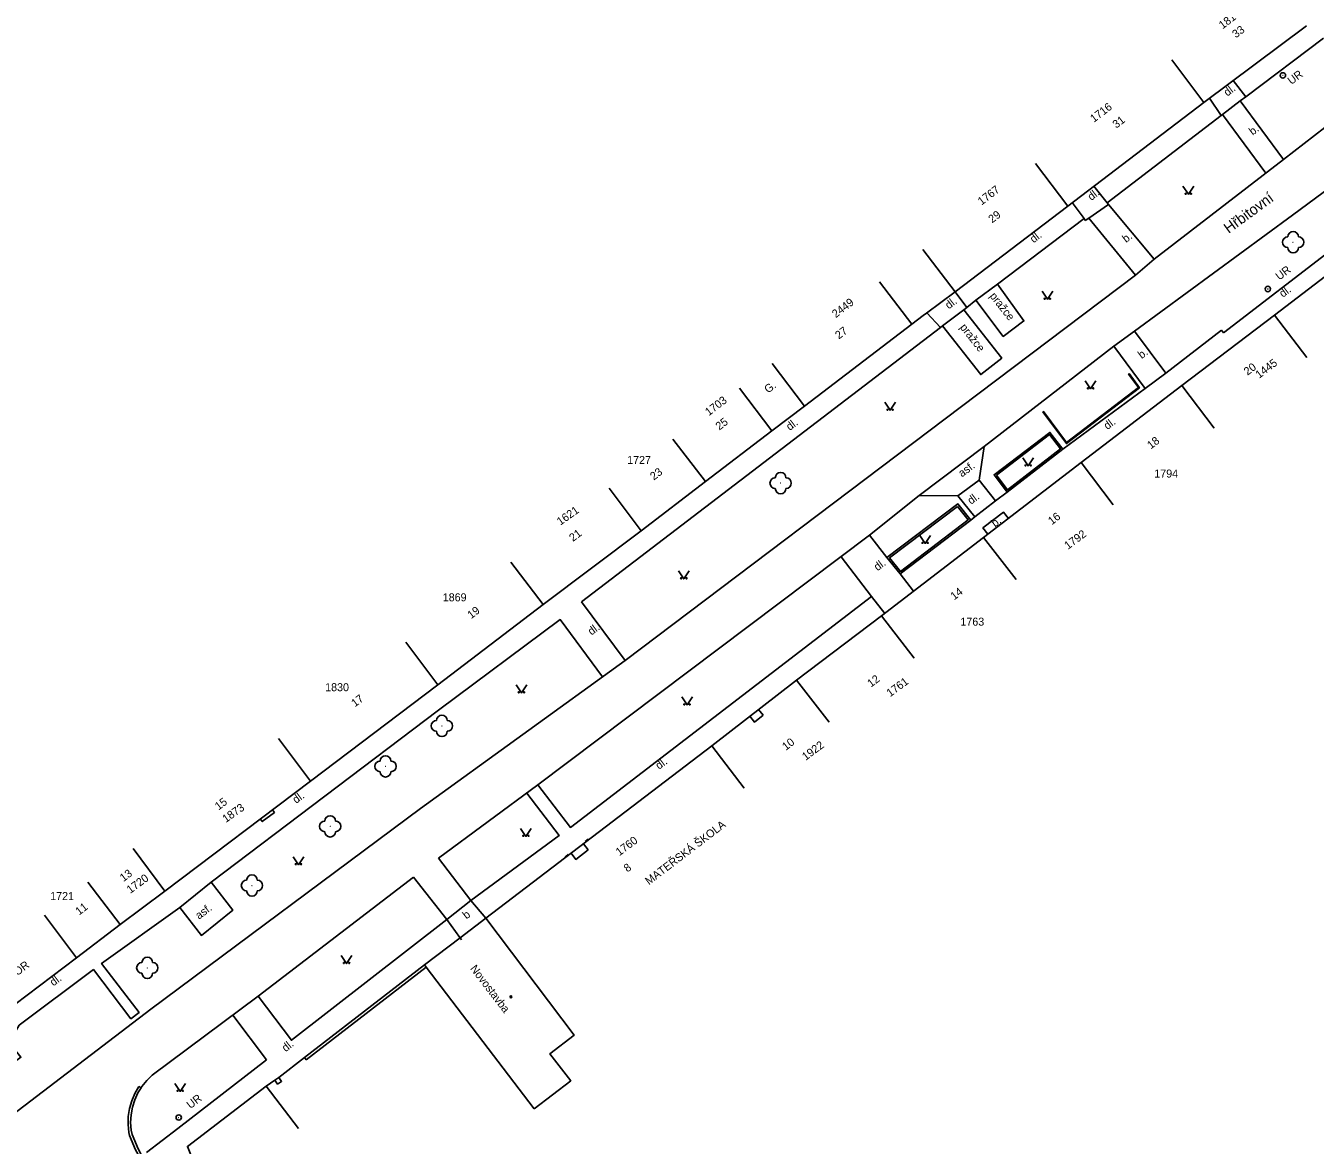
# Model space of a CAD drawing. Extents: x -584400 to -581602, y -1210894 to -1208793.
# Drawn here: x -582510.6 to -582389.8, y -1209260.4 to -1209155.5 of the extents above; entities that cross this region are included whole.
import ezdxf

# ---------------------------------------------------------------- set-up
doc = ezdxf.new("R2010")
doc.units = 0
for name, color, linetype in [('BUDOVY_MĚŘ', 7, 'Continuous'), ('NÁZVY_ULIC_TOK_SMĚR', 7, 'Continuous'), ('POMOC_POPIS', 7, 'Continuous'), ('ROZHRANÍ_PLOCH', 7, 'Continuous'), ('ZELEŇ', 7, 'Continuous'), ('ZN_BUDOV', 7, 'Continuous'), ('ZN_DOPLŇKOVÉ', 7, 'Continuous'), ('ZN_KULTUR', 7, 'Continuous'), ('Č_POPIS_EVID', 7, 'Continuous')]:
    doc.layers.add(name, color=color, linetype=linetype)

msp = doc.modelspace()

# ---------------------------------------------------------------- linework, layer by layer
at = {"layer": 'BUDOVY_MĚŘ'}
for points in [[(-582400.2, -1209162.7), (-582390.58, -1209155.51)], [(-582403.19, -1209158.7), (-582400.2, -1209162.7)], [(-582412.94, -1209172.41), (-582400.2, -1209162.7)], [(-582415.97, -1209168.43), (-582412.94, -1209172.41)], [(-582393.57, -1209182.62), (-582377.75, -1209170.54)], [(-582426.53, -1209176.46), (-582423.5, -1209180.44), (-582412.94, -1209172.41)], [(-582430.59, -1209179.49), (-582427.56, -1209183.47)], [(-582437.6, -1209191.13), (-582427.56, -1209183.47)], [(-582402.25, -1209189.22), (-582393.57, -1209182.62)], [(-582390.54, -1209186.59), (-582393.57, -1209182.62)], [(-582440.63, -1209187.15), (-582437.6, -1209191.13)], [(-582440.67, -1209193.46), (-582443.71, -1209189.47)], [(-582411.69, -1209196.42), (-582402.25, -1209189.22)], [(-582399.22, -1209193.2), (-582402.25, -1209189.22)], [(-582440.67, -1209193.46), (-582437.6, -1209191.13)], [(-582446.9, -1209198.2), (-582449.94, -1209194.23)], [(-582446.9, -1209198.2), (-582440.67, -1209193.46)], [(-582420.82, -1209203.43), (-582411.69, -1209196.42)], [(-582408.67, -1209200.39), (-582411.69, -1209196.42)], [(-582452.92, -1209202.81), (-582446.9, -1209198.2)], [(-582452.92, -1209202.81), (-582455.93, -1209198.82)], [(-582462.1, -1209209.73), (-582452.92, -1209202.81)], [(-582430.39, -1209210.79), (-582420.82, -1209203.43)], [(-582417.78, -1209207.39), (-582420.82, -1209203.43)], [(-582462.1, -1209209.73), (-582465.13, -1209205.75)], [(-582471.97, -1209217.25), (-582462.1, -1209209.73)], [(-582430.39, -1209210.79), (-582438.36, -1209216.8)], [(-582427.34, -1209214.75), (-582430.39, -1209210.79)], [(-582471.97, -1209217.25), (-582474.98, -1209213.26)], [(-582483.9, -1209226.26), (-582471.97, -1209217.25)], [(-582438.36, -1209216.8), (-582446.28, -1209222.95)], [(-582438.36, -1209216.8), (-582435.3, -1209220.75)], [(-582483.9, -1209226.26), (-582486.91, -1209222.27)], [(-582446.28, -1209222.95), (-582467.47, -1209239.11)], [(-582446.28, -1209222.95), (-582443.25, -1209226.92)], [(-582497.54, -1209236.56), (-582483.9, -1209226.26)], [(-582497.54, -1209236.56), (-582500.53, -1209232.56)], [(-582501.73, -1209239.69), (-582504.76, -1209235.71)], [(-582501.73, -1209239.69), (-582497.54, -1209236.56)], [(-582505.82, -1209242.8), (-582508.83, -1209238.81)], [(-582467.47, -1209239.11), (-582469.88, -1209240.94), (-582473.22, -1209243.48), (-582473.07, -1209243.68), (-582462.93, -1209256.94)], [(-582467.47, -1209239.11), (-582459.2, -1209250.06), (-582461.46, -1209251.79), (-582459.51, -1209254.33), (-582462.93, -1209256.94)], [(-582505.82, -1209242.8), (-582501.73, -1209239.69)], [(-582515.1, -1209249.79), (-582505.82, -1209242.8)], [(-582488.06, -1209254.83), (-582495.44, -1209260.47), (-582489.61, -1209275.17)], [(-582488.06, -1209254.83), (-582485.03, -1209258.81)]]:
    msp.add_lwpolyline(points, dxfattribs=at)
at = {"layer": 'ROZHRANÍ_PLOCH'}
for points in [[(-582392.73, -1209168.05), (-582380.13, -1209158.29), (-582375.26, -1209154.89), (-582365.39, -1209148.17), (-582355.61, -1209141), (-582340.78, -1209130.73)], [(-582396.24, -1209162.16), (-582388.96, -1209156.68)], [(-582406.67, -1209184.13), (-582391.87, -1209173.27), (-582380.85, -1209165.11), (-582372.27, -1209159.23)], [(-582397.45, -1209160.65), (-582396.24, -1209162.16)], [(-582399.66, -1209162.3), (-582398.56, -1209163.93)], [(-582398.44, -1209163.84), (-582396.77, -1209162.56)], [(-582396.77, -1209162.56), (-582396.24, -1209162.16)], [(-582396.77, -1209162.56), (-582392.73, -1209168.05)], [(-582409.24, -1209172.1), (-582398.56, -1209163.93)], [(-582398.56, -1209163.93), (-582398.44, -1209163.84)], [(-582398.44, -1209163.84), (-582394.39, -1209169.33)], [(-582404.83, -1209177.37), (-582392.73, -1209168.05)], [(-582410.5, -1209170.54), (-582409.24, -1209172.1)], [(-582411.4, -1209173.57), (-582412.52, -1209172.08)], [(-582410.98, -1209173.54), (-582409.11, -1209172.25)], [(-582409.11, -1209172.25), (-582409.24, -1209172.1)], [(-582404.83, -1209177.37), (-582409.11, -1209172.25)], [(-582419.52, -1209179.71), (-582411.4, -1209173.57)], [(-582411.4, -1209173.57), (-582411.3, -1209173.74)], [(-582410.98, -1209173.54), (-582411.3, -1209173.74)], [(-582410.98, -1209173.54), (-582406.6, -1209178.86)], [(-582398.34, -1209184.27), (-582387.93, -1209176.29)], [(-582406.6, -1209178.86), (-582404.83, -1209177.37)], [(-582422.91, -1209191.16), (-582406.6, -1209178.86)], [(-582419.52, -1209179.71), (-582417.05, -1209183.16), (-582418.98, -1209184.61), (-582421.56, -1209181.23)], [(-582421.56, -1209181.23), (-582419.52, -1209179.71)], [(-582423.5, -1209180.44), (-582422.4, -1209181.9)], [(-582422.4, -1209181.9), (-582421.56, -1209181.23)], [(-582426.15, -1209182.4), (-582424.88, -1209183.77)], [(-582424.69, -1209183.63), (-582422.68, -1209182.12)], [(-582422.68, -1209182.12), (-582419.13, -1209186.64), (-582421.1, -1209188.19), (-582424.69, -1209183.63)], [(-582422.68, -1209182.12), (-582422.4, -1209181.9)], [(-582424.69, -1209183.63), (-582424.88, -1209183.77)], [(-582424.88, -1209183.77), (-582458.5, -1209209.48)], [(-582408.61, -1209185.52), (-582406.67, -1209184.13)], [(-582406.67, -1209184.13), (-582403.75, -1209188.06)], [(-582403.75, -1209188.06), (-582398.53, -1209184.03)], [(-582398.34, -1209184.27), (-582398.53, -1209184.03)], [(-582420.77, -1209194.93), (-582408.61, -1209185.52)], [(-582408.61, -1209185.52), (-582405.69, -1209189.49)], [(-582415.26, -1209191.69), (-582413.07, -1209194.65), (-582406.23, -1209189.42), (-582407.18, -1209188.1)], [(-582415.26, -1209191.69), (-582415.2, -1209191.65), (-582413.05, -1209194.55), (-582406.32, -1209189.4), (-582407.24, -1209188.14), (-582407.18, -1209188.1)], [(-582405.69, -1209189.49), (-582403.75, -1209188.06)], [(-582405.69, -1209189.49), (-582413.41, -1209195.18)], [(-582422.91, -1209191.16), (-582454.42, -1209214.96)], [(-582413.41, -1209195.18), (-582414.61, -1209193.6), (-582419.84, -1209197.57), (-582418.62, -1209199.2)], [(-582419.63, -1209197.6), (-582418.59, -1209198.99), (-582413.62, -1209195.15), (-582414.64, -1209193.81), (-582419.63, -1209197.6)], [(-582426.85, -1209199.52), (-582420.77, -1209194.93)], [(-582421.24, -1209198.06), (-582420.77, -1209194.93)], [(-582418.62, -1209199.2), (-582413.41, -1209195.18)], [(-582423.24, -1209199.55), (-582421.24, -1209198.06)], [(-582419.7, -1209200), (-582421.24, -1209198.06)], [(-582418.62, -1209199.2), (-582419.7, -1209200)], [(-582431.52, -1209203.24), (-582426.85, -1209199.52)], [(-582422.03, -1209201.81), (-582423.24, -1209200.3), (-582429.88, -1209205.33)], [(-582423.27, -1209200.53), (-582429.63, -1209205.36), (-582428.62, -1209206.62), (-582422.27, -1209201.78), (-582423.27, -1209200.53)], [(-582426.85, -1209199.52), (-582423.24, -1209199.55)], [(-582423.24, -1209199.55), (-582421.66, -1209201.52)], [(-582421.66, -1209201.52), (-582419.7, -1209200)], [(-582428.64, -1209206.85), (-582422.03, -1209201.81)], [(-582421.66, -1209201.52), (-582422.03, -1209201.81)], [(-582418.5, -1209201.65), (-582418.95, -1209201.08), (-582420.89, -1209202.55), (-582420.44, -1209203.14)], [(-582462.59, -1209226.62), (-582431.52, -1209203.24)], [(-582429.88, -1209205.33), (-582431.52, -1209203.24)], [(-582434.17, -1209205.24), (-582431.32, -1209208.96)], [(-582429.88, -1209205.33), (-582428.64, -1209206.85)], [(-582427.39, -1209208.48), (-582428.64, -1209206.85)], [(-582431.32, -1209208.96), (-582459.55, -1209230.59), (-582462.59, -1209226.62)], [(-582430.09, -1209210.56), (-582431.32, -1209208.96)], [(-582454.42, -1209214.96), (-582458.5, -1209209.48)], [(-582493.2, -1209235.73), (-582471.92, -1209219.63), (-582460.5, -1209211.14), (-582456.53, -1209216.49)], [(-582454.42, -1209214.96), (-582473.58, -1209228.82), (-582498.86, -1209247.61), (-582520.87, -1209264.4), (-582538.55, -1209278.13)], [(-582441.49, -1209220.09), (-582441.91, -1209219.55)], [(-582441.49, -1209220.09), (-582442.31, -1209220.73), (-582442.73, -1209220.19)], [(-582471.92, -1209233.48), (-582462.59, -1209226.62)], [(-582463.64, -1209227.38), (-582460.6, -1209231.35), (-582468.88, -1209237.44), (-582467.47, -1209239.11)], [(-582487.47, -1209228.95), (-582487.28, -1209229.19), (-582488.42, -1209230.05), (-582488.6, -1209229.81)], [(-582458.16, -1209231.92), (-582457.89, -1209231.71), (-582457.84, -1209231.77)], [(-582458.16, -1209231.92), (-582458.11, -1209231.97)], [(-582459.75, -1209233.13), (-582460.02, -1209233.34), (-582459.97, -1209233.39)], [(-582459.75, -1209233.13), (-582459.7, -1209233.19)], [(-582457.89, -1209232.71), (-582459.04, -1209233.59), (-582459.48, -1209233.02)], [(-582457.89, -1209232.71), (-582458.33, -1209232.14)], [(-582471.92, -1209233.48), (-582468.88, -1209237.44)], [(-582488.82, -1209246.4), (-582474.25, -1209235.27)], [(-582471.14, -1209239.23), (-582474.25, -1209235.27)], [(-582493.2, -1209235.73), (-582491.17, -1209238.34), (-582494.13, -1209240.72), (-582496.16, -1209238.11)], [(-582496.16, -1209238.11), (-582493.2, -1209235.73)], [(-582541.38, -1209275.07), (-582520.64, -1209259.31), (-582511.04, -1209252.13), (-582512.14, -1209250.73), (-582511.19, -1209249.12), (-582504.25, -1209243.91), (-582500.73, -1209248.51), (-582499.97, -1209247.92), (-582503.48, -1209243.34), (-582496.16, -1209238.11)], [(-582468.88, -1209237.44), (-582471.14, -1209239.23)], [(-582471.14, -1209239.23), (-582485.7, -1209250.53), (-582488.82, -1209246.4)], [(-582471.14, -1209239.23), (-582469.9, -1209240.92)], [(-582498.73, -1209253.81), (-582488.82, -1209246.4)], [(-582491.19, -1209248.17), (-582488.02, -1209252.37)], [(-582499.27, -1209261.03), (-582496.35, -1209258.8), (-582488.02, -1209252.37)], [(-582498.73, -1209253.81), (-582499.25, -1209254.3), (-582499.7, -1209254.86), (-582499.78, -1209254.99)], [(-582499.98, -1209254.86), (-582500.36, -1209255.51), (-582500.66, -1209256.2), (-582500.86, -1209256.92), (-582500.98, -1209257.67), (-582501, -1209258.42), (-582500.92, -1209259.17), (-582500.87, -1209259.44), (-582500.29, -1209260.81), (-582499.54, -1209262.1), (-582498.84, -1209263.05)], [(-582499.78, -1209254.99), (-582500.08, -1209255.47), (-582500.38, -1209256.12), (-582500.59, -1209256.8), (-582500.72, -1209257.51), (-582500.76, -1209258.23), (-582500.7, -1209258.94), (-582500.63, -1209259.36), (-582500.06, -1209260.7), (-582499.71, -1209261.36)], [(-582499.98, -1209254.86), (-582499.78, -1209254.99)]]:
    msp.add_lwpolyline(points, dxfattribs=at)
at = {"layer": 'ZELEŇ'}
for centre in [(-582391.82, -1209175.79), (-582439.85, -1209198.35), (-582471.59, -1209221.09), (-582476.87, -1209224.88), (-582482.06, -1209230.5), (-582489.39, -1209236.04), (-582499.2, -1209243.75)]:
    msp.add_circle(centre, 0.0005, dxfattribs=at)
for centre, start, end in [((-582392.32, -1209175.79), 90, 270), ((-582391.82, -1209175.29), 0, 180), ((-582391.32, -1209175.79), 270, 90), ((-582391.82, -1209176.29), 180, 360), ((-582440.35, -1209198.35), 90, 270), ((-582439.85, -1209197.85), 0, 180), ((-582439.35, -1209198.35), 270, 90), ((-582439.85, -1209198.85), 180, 360), ((-582472.09, -1209221.09), 90, 270), ((-582471.59, -1209220.59), 0, 180), ((-582471.09, -1209221.09), 270, 90), ((-582471.59, -1209221.59), 180, 360), ((-582477.37, -1209224.88), 90, 270), ((-582476.87, -1209224.38), 0, 180), ((-582476.37, -1209224.88), 270, 90), ((-582476.87, -1209225.38), 180, 360), ((-582482.06, -1209230), 0, 180), ((-582482.56, -1209230.5), 90, 270), ((-582481.56, -1209230.5), 270, 90), ((-582482.06, -1209231), 180, 360), ((-582489.89, -1209236.04), 90, 270), ((-582489.39, -1209235.54), 0, 180), ((-582488.89, -1209236.04), 270, 90), ((-582489.39, -1209236.54), 180, 360), ((-582499.2, -1209243.25), 0, 180), ((-582499.7, -1209243.75), 90, 270), ((-582498.7, -1209243.75), 270, 90), ((-582499.2, -1209244.25), 180, 360)]:
    msp.add_arc(centre, 0.5, start, end, dxfattribs=at)
at = {"layer": 'ZN_BUDOV'}
msp.add_circle((-582465.12, -1209246.46), 0.0875, dxfattribs=at)
at = {"layer": 'ZN_DOPLŇKOVÉ'}
for points in [[(-582426.19, -1209182.43), (-582423.5, -1209180.44)], [(-582426.5, -1209182.66), (-582426.19, -1209182.43)], [(-582427.56, -1209183.47), (-582426.5, -1209182.66)], [(-582469.88, -1209240.94), (-582469.75, -1209241.12)], [(-582484.31, -1209252.35), (-582484.47, -1209252.15), (-582473.22, -1209243.48)], [(-582473.07, -1209243.68), (-582484.31, -1209252.35)], [(-582484.47, -1209252.15), (-582486.88, -1209254.01)], [(-582487.25, -1209254.27), (-582488.06, -1209254.83)], [(-582487.25, -1209254.27), (-582486.88, -1209254.01), (-582486.62, -1209254.38), (-582486.99, -1209254.64), (-582487.25, -1209254.27)]]:
    msp.add_lwpolyline(points, dxfattribs=at)
for centre, radius in [((-582392.78, -1209160.16), 0.25), ((-582392.78, -1209160.16), 0.0005), ((-582394.19, -1209180.17), 0.25), ((-582394.19, -1209180.17), 0.0005), ((-582496.25, -1209257.77), 0.25), ((-582496.25, -1209257.77), 0.0005)]:
    msp.add_circle(centre, radius, dxfattribs=at)
at = {"layer": 'ZN_KULTUR'}
for points in [[(-582402.14, -1209170.55), (-582401.64, -1209171.3), (-582401.14, -1209170.55)], [(-582415.35, -1209180.38), (-582414.85, -1209181.13), (-582414.35, -1209180.38)], [(-582411.3, -1209188.77), (-582410.8, -1209189.52), (-582410.3, -1209188.77)], [(-582430.09, -1209190.78), (-582429.59, -1209191.53), (-582429.09, -1209190.78)], [(-582417.15, -1209195.99), (-582416.65, -1209196.74), (-582416.15, -1209195.99)], [(-582426.8, -1209203.25), (-582426.3, -1209204), (-582425.8, -1209203.25)], [(-582449.42, -1209206.57), (-582448.92, -1209207.32), (-582448.42, -1209206.57)], [(-582464.64, -1209217.25), (-582464.14, -1209218), (-582463.64, -1209217.25)], [(-582449.12, -1209218.38), (-582448.62, -1209219.13), (-582448.12, -1209218.38)], [(-582464.22, -1209230.69), (-582463.72, -1209231.44), (-582463.22, -1209230.69)], [(-582485.53, -1209233.34), (-582485.03, -1209234.09), (-582484.53, -1209233.34)], [(-582481.02, -1209242.6), (-582480.52, -1209243.35), (-582480.02, -1209242.6)], [(-582496.61, -1209254.57), (-582496.11, -1209255.32), (-582495.61, -1209254.57)]]:
    msp.add_lwpolyline(points, dxfattribs=at)
for centre in [(-582401.89, -1209171.25), (-582401.39, -1209171.25), (-582415.1, -1209181.08), (-582414.6, -1209181.08), (-582411.05, -1209189.47), (-582410.55, -1209189.47), (-582429.84, -1209191.48), (-582429.34, -1209191.48), (-582416.9, -1209196.69), (-582416.4, -1209196.69), (-582426.55, -1209203.95), (-582426.05, -1209203.95), (-582449.17, -1209207.27), (-582448.67, -1209207.27), (-582464.39, -1209217.95), (-582463.89, -1209217.95), (-582448.87, -1209219.08), (-582448.37, -1209219.08), (-582463.97, -1209231.39), (-582463.47, -1209231.39), (-582485.28, -1209234.04), (-582484.78, -1209234.04), (-582480.77, -1209243.3), (-582480.27, -1209243.3), (-582496.36, -1209255.27), (-582495.86, -1209255.27)]:
    msp.add_circle(centre, 0.05, dxfattribs=at)

# ---------------------------------------------------------------- texts
at = {"layer": 'NÁZVY_ULIC_TOK_SMĚR'}
msp.add_text('Hřbitovní', height=1, rotation=36.2832, dxfattribs=at).set_placement((-582397.86, -1209175.02))
at = {"layer": 'POMOC_POPIS'}
for s, rotation, p in [('UR', 36.7898, (-582391.99, -1209161.07)), ('dl.', 37.3967, (-582397.98, -1209162.16)), ('b.', 37.3967, (-582395.61, -1209165.81)), ('dl.', 37.3967, (-582410.73, -1209171.93)), ('dl.', 37.3967, (-582416.14, -1209175.9)), ('b.', 37.3967, (-582407.48, -1209175.87)), ('UR', 37.4794, (-582393.11, -1209179.39)), ('dl.', 36.7132, (-582392.78, -1209181)), ('dl.', 37.3967, (-582424.09, -1209182.09)), ('pražce', 308.2176, (-582420.3, -1209180.84)), ('pražce', 308.2176, (-582423.09, -1209183.77)), ('b.', 36.7132, (-582406.02, -1209186.74)), ('G.', 37.0166, (-582441.03, -1209189.97)), ('dl.', 37.3967, (-582438.99, -1209193.47)), ('dl.', 36.7132, (-582409.23, -1209193.39)), ('asf.', 36.7132, (-582422.86, -1209197.83)), ('dl.', 36.7132, (-582422, -1209200.39)), ('b.', 36.7132, (-582419.76, -1209202.51)), ('dl.', 36.7132, (-582430.77, -1209206.61)), ('dl.', 36.7142, (-582457.57, -1209212.64)), ('dl.', 36.7132, (-582451.24, -1209225.21)), ('dl.', 36.7142, (-582485.25, -1209228.4)), ('MATEŘSKÁ ŠKOLA', 37.3434, (-582452.19, -1209236.02)), ('asf.', 36.7142, (-582494.36, -1209239.25)), ('b', 38.3551, (-582469.29, -1209239.23)), ('ZBOR', 36.9824, (-582512.4, -1209245.3)), ('Novostavba', 307.4969, (-582468.98, -1209243.83)), ('dl.', 36.7142, (-582508, -1209245.5)), ('dl.', 38.3551, (-582486.23, -1209251.66)), ('UR', 37.5427, (-582495.16, -1209256.99))]:
    msp.add_text(s, height=0.75, rotation=rotation, dxfattribs=at).set_placement(p)
at = {"layer": 'Č_POPIS_EVID'}
for s, rotation, p in [('1814', 37.365, (-582398.43, -1209155.86)), ('33', 36.7898, (-582397.18, -1209156.7)), ('1716', 37.365, (-582410.49, -1209164.61)), ('31', 37.2762, (-582408.39, -1209165.16)), ('1767', 37.2604, (-582421.02, -1209172.36)), ('29', 37.2604, (-582420.03, -1209174.03)), ('2449', 37.3333, (-582434.68, -1209182.91)), ('27', 37.3333, (-582434.39, -1209184.91)), ('20', 37.2882, (-582396.09, -1209188.3)), ('1445', 37.2882, (-582395, -1209188.59)), ('1703', 37.3333, (-582446.58, -1209192.09)), ('25', 37.2918, (-582445.59, -1209193.43)), ('18', 37.3003, (-582405.15, -1209195.2)), ('23', 37.4198, (-582451.73, -1209198.12)), ('1621', 35.1919, (-582460.49, -1209202.34)), ('16', 37.5319, (-582414.43, -1209202.3)), ('21', 37.0106, (-582459.31, -1209203.87)), ('1792', 36.5607, (-582412.92, -1209204.6)), ('14', 37.5912, (-582423.58, -1209209.34)), ('19', 37.3249, (-582468.85, -1209211.1)), ('12', 37.0168, (-582431.38, -1209217.51)), ('1761', 36.5607, (-582429.58, -1209218.41)), ('17', 37.0532, (-582479.74, -1209219.36)), ('10', 37.7923, (-582439.35, -1209223.43)), ('1922', 36.5607, (-582437.5, -1209224.37)), ('15', 37.0609, (-582492.52, -1209229.02)), ('1873', 35.1919, (-582491.84, -1209230.19)), ('1760', 36.5607, (-582454.96, -1209233.3)), ('8', 37.3434, (-582454.2, -1209234.83)), ('13', 36.7142, (-582501.43, -1209235.72)), ('1720', 36.5607, (-582500.79, -1209236.83)), ('11', 37.2487, (-582505.59, -1209238.86))]:
    msp.add_text(s, height=0.75, rotation=rotation, dxfattribs=at).set_placement(p)
for s, p in [('1727', (-582454.23, -1209196.56)), ('1794', (-582404.83, -1209197.83)), ('1869', (-582471.51, -1209209.42)), ('1763', (-582423, -1209211.7)), ('1830', (-582482.53, -1209217.84)), ('1721', (-582508.3, -1209237.4))]:
    msp.add_text(s, height=0.75, dxfattribs=at).set_placement(p)

doc.saveas('drawing.dxf')
